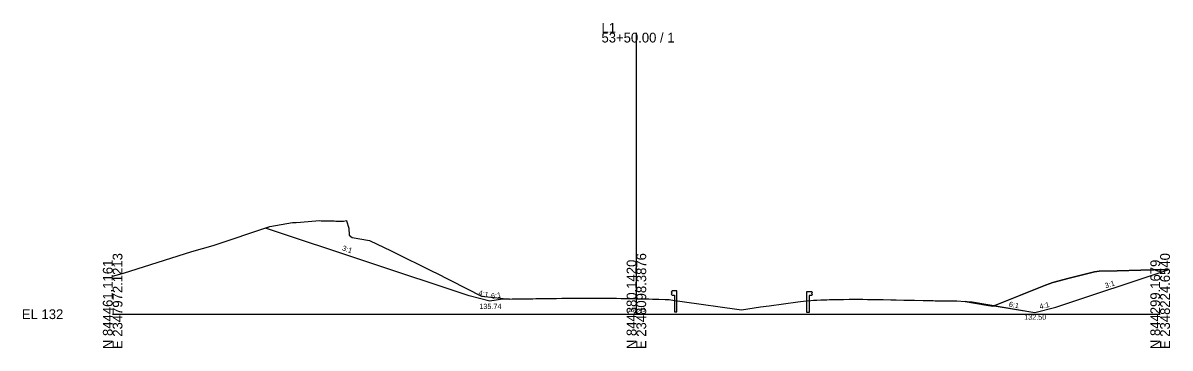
# Model space of a CAD drawing. Extents: x -26 to 2348258, y -10 to 844496.
# Drawn here: x 1275.5 to 1604, y 4490.3 to 4583.4 of the extents above; entities that cross this region are included whole.
import ezdxf

# ---------------------------------------------------------------- set-up
doc = ezdxf.new("R2010")
doc.units = 0
for name, color, linetype in [('Exist Cross Section Cell', 7, 'Continuous'), ('Exist XS Center Line Elevation Label', 7, 'Continuous'), ('Exist XS Ground Line', 7, 'Continuous'), ('Prop CMT Guardrail Graphics', 7, 'Continuous'), ('Prop CMT Slope Grass', 7, 'Continuous'), ('Prop XS Earthwork Shape', 7, 'Continuous'), ('Prop XS SE Text', 7, 'Continuous')]:
    doc.layers.add(name, color=color, linetype=linetype)

msp = doc.modelspace()

# ---------------------------------------------------------------- linework, layer by layer
at = {"layer": 'Exist Cross Section Cell'}
for p, q in [((1451.19, 4500), (1451.19, 4580.57)), ((1301.19, 4500), (1451.19, 4500)), ((1451.19, 4500), (1601.19, 4500))]:
    msp.add_line(p, q, dxfattribs=at)
at = {"layer": 'Exist XS Ground Line'}
msp.add_lwpolyline([(1301.19, 4510.88), (1304.25, 4511.75), (1323.88, 4517.9), (1330, 4519.7), (1346.22, 4525.06), (1352.69, 4526.21), (1353.06, 4526.23), (1353.75, 4526.24), (1355.03, 4526.3), (1360.47, 4526.79), (1360.88, 4526.77), (1361.75, 4526.75), (1363.91, 4526.68), (1364.59, 4526.7), (1365.08, 4526.67), (1366.51, 4526.65), (1366.93, 4526.65), (1367.27, 4526.64), (1368.16, 4526.86), (1368.21, 4526.74), (1368.86, 4524.64), (1368.9, 4522.58), (1369.75, 4521.94), (1374.72, 4521.12), (1380.96, 4518.1), (1393.23, 4512.07), (1393.55, 4511.9), (1406.82, 4505.18), (1414.83, 4504.34), (1415.61, 4504.35), (1416.02, 4504.36), (1417.97, 4504.39), (1418.33, 4504.4), (1420.94, 4504.43), (1421.5, 4504.44), (1422.4, 4504.45), (1423.32, 4504.46), (1423.88, 4504.47), (1426.97, 4504.51), (1427.46, 4504.51), (1428.33, 4504.52), (1429.82, 4504.55), (1430.56, 4504.55), (1431.67, 4504.56), (1432.81, 4504.57), (1434.15, 4504.58), (1435.99, 4504.6), (1436.31, 4504.6), (1438.74, 4504.61), (1439.73, 4504.6), (1441.04, 4504.6), (1441.68, 4504.59), (1443.08, 4504.58), (1444.64, 4504.56), (1445.52, 4504.54), (1446.8, 4504.52), (1447.63, 4504.5), (1448.63, 4504.48), (1450.12, 4504.45), (1450.52, 4504.45), (1451.19, 4504.43), (1452.71, 4504.4), (1453.52, 4504.37), (1454.75, 4504.35), (1455.81, 4504.32), (1456.5, 4504.31), (1457.65, 4504.28), (1459.44, 4504.22), (1460.53, 4504.17), (1461.01, 4504.15), (1461.63, 4504.05), (1464.93, 4503.55), (1479.93, 4501.48), (1481.33, 4501.29), (1486.78, 4502.06), (1489.23, 4502.4), (1497.47, 4503.55), (1499.81, 4503.81), (1501.11, 4503.95), (1501.87, 4504.04), (1502.86, 4504.04), (1504.04, 4504.1), (1505.72, 4504.14), (1506.49, 4504.16), (1506.94, 4504.17), (1508.3, 4504.19), (1509.98, 4504.23), (1510.54, 4504.24), (1512.15, 4504.27), (1513.01, 4504.27), (1513.74, 4504.27), (1514.92, 4504.27), (1516, 4504.26), (1517.38, 4504.25), (1519.14, 4504.22), (1519.58, 4504.21), (1521.01, 4504.18), (1521.82, 4504.17), (1524.1, 4504.12), (1524.45, 4504.11), (1524.81, 4504.11), (1525.62, 4504.1), (1527.8, 4504.06), (1528.24, 4504.05), (1528.93, 4504.04), (1530.83, 4504.01), (1533.33, 4503.95), (1533.84, 4503.94), (1535.85, 4503.91), (1536.23, 4503.9), (1536.8, 4503.87), (1538.15, 4503.84), (1539.03, 4503.84), (1539.58, 4503.82), (1540.79, 4503.8), (1542.92, 4503.78), (1545.32, 4503.66), (1551.44, 4502.6), (1553.29, 4502.27), (1568.37, 4508.33), (1570.44, 4509.09), (1575.16, 4510.3), (1582.43, 4512.1), (1583.74, 4512.29), (1588.92, 4512.41), (1595.62, 4512.62), (1599.37, 4512.73), (1603.8, 4512.82)], dxfattribs=at)
at = {"layer": 'Prop CMT Guardrail Graphics'}
for p, q in [((1461.46, 4506.64), (1461.19, 4506.35)), ((1461.19, 4506.35), (1461.46, 4506.06)), ((1461.46, 4506.06), (1461.19, 4505.77)), ((1461.19, 4505.77), (1461.46, 4505.47)), ((1462.79, 4506.64), (1461.46, 4506.64)), ((1461.46, 4505.47), (1462.13, 4505.47)), ((1462.13, 4505.47), (1462.13, 4500.64)), ((1462.79, 4500.64), (1462.79, 4506.64)), ((1500.02, 4500.51), (1500.02, 4506.51)), ((1500.02, 4506.51), (1501.35, 4506.51)), ((1501.35, 4505.35), (1500.68, 4505.35)), ((1500.68, 4505.35), (1500.68, 4500.51)), ((1501.35, 4506.51), (1501.62, 4506.22)), ((1501.62, 4506.22), (1501.35, 4505.93)), ((1501.35, 4505.93), (1501.62, 4505.64)), ((1501.62, 4505.64), (1501.35, 4505.35)), ((1462.13, 4500.64), (1462.79, 4500.64)), ((1500.68, 4500.51), (1500.02, 4500.51))]:
    msp.add_line(p, q, dxfattribs=at)
at = {"layer": 'Prop CMT Slope Grass'}
for p, q in [((1403.25, 4505.24), (1345, 4524.66)), ((1571.32, 4502), (1603.8, 4512.82)), ((1409.25, 4503.74), (1403.25, 4505.24)), ((1412.83, 4504.34), (1409.25, 4503.74)), ((1414.83, 4504.34), (1412.83, 4504.34)), ((1545.32, 4503.66), (1547.32, 4503.5)), ((1547.32, 4503.5), (1565.32, 4500.5)), ((1565.32, 4500.5), (1571.32, 4502))]:
    msp.add_line(p, q, dxfattribs=at)
at = {"layer": 'Prop XS Earthwork Shape'}
for points in [[(1406.82, 4505.18), (1414.83, 4504.34), (1412.83, 4504.34), (1409.25, 4503.74), (1403.25, 4505.24), (1345, 4524.66), (1346.22, 4525.06), (1352.69, 4526.21), (1353.06, 4526.23), (1353.75, 4526.24), (1355.03, 4526.3), (1360.47, 4526.79), (1360.88, 4526.77), (1361.75, 4526.75), (1363.91, 4526.68), (1364.59, 4526.7), (1365.08, 4526.67), (1366.51, 4526.65), (1366.93, 4526.65), (1367.27, 4526.64), (1368.16, 4526.86), (1368.21, 4526.74), (1368.86, 4524.64), (1368.9, 4522.58), (1369.75, 4521.94), (1374.72, 4521.12), (1380.96, 4518.1), (1393.23, 4512.07), (1393.55, 4511.9)], [(1571.32, 4502), (1603.8, 4512.82), (1599.37, 4512.73), (1595.62, 4512.62), (1588.92, 4512.41), (1583.74, 4512.29), (1582.43, 4512.1), (1575.16, 4510.3), (1570.44, 4509.09), (1568.37, 4508.33), (1553.7, 4502.43), (1565.32, 4500.5)], [(1545.32, 4503.66), (1547.32, 4503.5), (1553.7, 4502.43), (1553.29, 4502.27), (1551.44, 4502.6)]]:
    msp.add_lwpolyline(points, close=True, dxfattribs=at)

# ---------------------------------------------------------------- texts
at = {"layer": 'Exist Cross Section Cell'}
for s, p in [('L1', (1441.19, 4580.57)), ('53+50.00 / 1', (1441.19, 4577.77)), ('EL 132', (1275.19, 4498.6))]:
    msp.add_text(s, height=2.8, dxfattribs=at).set_placement(p)
for s, p in [('E 2348224.6540', (1603.99, 4490)), ('N 844461.1161', (1301.19, 4490)), ('E 2347972.1213', (1303.99, 4490)), ('N 844380.1420', (1451.19, 4490)), ('E 2348098.3876', (1453.99, 4490)), ('N 844299.1679', (1601.19, 4490))]:
    msp.add_text(s, height=2.8, rotation=90, dxfattribs=at).set_placement(p)
at = {"layer": 'Exist XS Center Line Elevation Label'}
msp.add_text('136.43', height=1.2, dxfattribs=at).set_placement((1448.72, 4500.64))
at = {"layer": 'Prop XS SE Text'}
for s, rotation, p in [('3:1', 341.5651, (1366.79, 4518.32)), ('3:1', 18.4349, (1585.62, 4507.38)), ('4:1', 345.9638, (1405.84, 4505.48)), ('6:1', 9.4623, (1409.71, 4504.38)), ('6:1', 350.5377, (1557.79, 4502.15)), ('4:1', 14.0362, (1566.82, 4501.41))]:
    msp.add_text(s, height=1.5, rotation=rotation, dxfattribs=at).set_placement(p)
for s, p in [('135.74', (1406.21, 4501.48)), ('132.50', (1562.24, 4498.41))]:
    msp.add_text(s, height=1.5, dxfattribs=at).set_placement(p)

doc.saveas('drawing.dxf')
